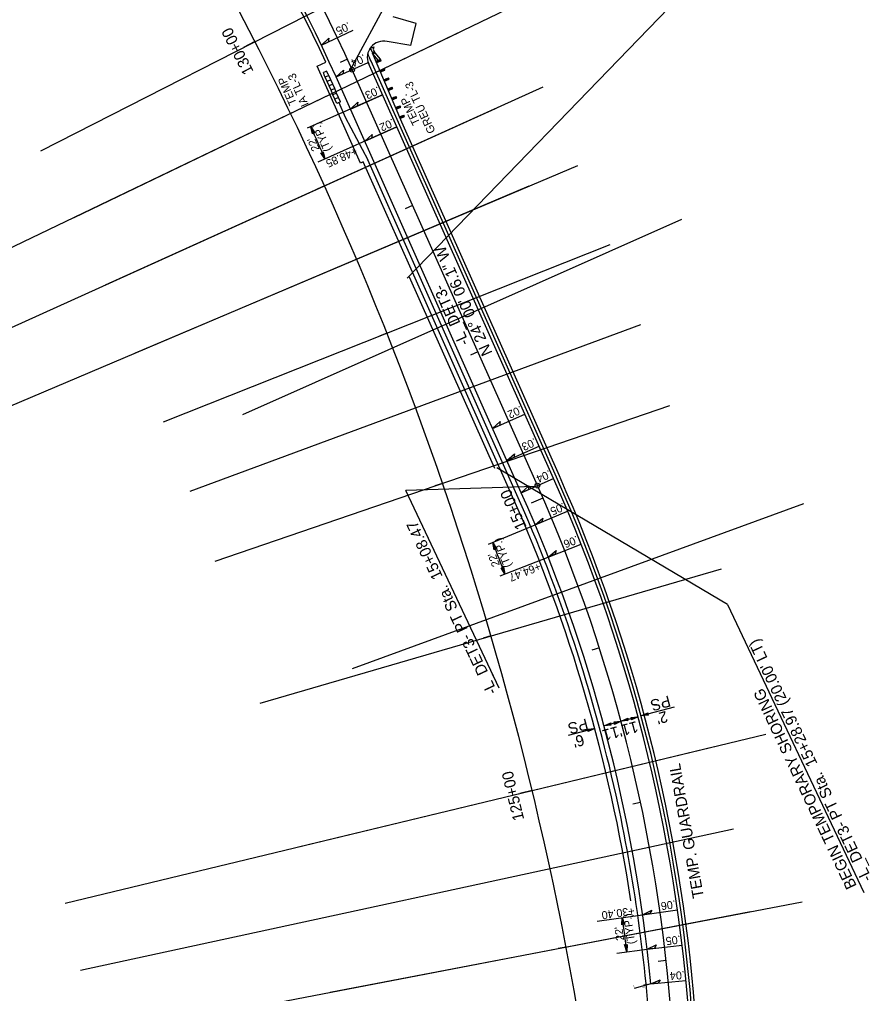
# Model space of a CAD drawing. Extents: x 473658 to 481584, y 489119 to 506230.
# Drawn here: x 477538 to 478069, y 498967 to 499575 of the extents above; entities that cross this region are included whole.
import ezdxf

# ---------------------------------------------------------------- set-up
doc = ezdxf.new("R2010")
doc.units = 0
for name, color, linetype in [('Exist Structure Minor Culvert Topo', 7, 'Continuous'), ('Exist Structure Minor Pipes CMP 60 Inch', 7, 'Continuous'), ('Exist Structure Minor Pipes RCP 12 Inch Leader', 7, 'Continuous'), ('Prop Conc Barrier', 7, 'Continuous'), ('Prop Dimension', 7, 'Continuous'), ('Prop EOT', 7, 'Continuous'), ('Prop Guardrail', 7, 'Continuous'), ('Prop Guardrail Anchor Unit CELL', 7, 'Continuous'), ('Prop Horizontal Alignment', 7, 'Continuous'), ('Prop Horizontal Alignment Direction Label', 7, 'Continuous'), ('Prop Horizontal Alignment Station Label', 7, 'Continuous'), ('Prop Horizontal Alignment Tick Label', 7, 'Continuous'), ('Prop Horizontal Alignment Tick Large', 7, 'Continuous'), ('Prop Horizontal Alignment Tick Small', 7, 'Continuous'), ('Prop Paved Shoulder', 7, 'Continuous'), ('Prop Superelevation  Arrow CELL', 7, 'Continuous'), ('Prop Superelevation Label', 7, 'Continuous'), ('Scratch_Level_5', 7, 'Continuous'), ('Scratch_Level_6', 7, 'Continuous'), ('Sheet Plan And Profile CELL', 7, 'Continuous'), ('Sheet Profile Grid Major CELL', 7, 'Continuous')]:
    doc.layers.add(name, color=color, linetype=linetype)

msp = doc.modelspace()

# ---------------------------------------------------------------- linework, layer by layer
at = {"layer": 'Exist Structure Minor Pipes CMP 60 Inch'}
msp.add_line((477834.89, 499294.51), (477781.59, 499414.21), dxfattribs=at)
at = {"layer": 'Exist Structure Minor Pipes RCP 12 Inch Leader'}
for p, q in [((477728.91, 499542.35), (477728, 499541.94)), ((477728.59, 499540.01), (477728, 499541.94)), ((477728.99, 499539.1), (477728.59, 499540.01)), ((477729.83, 499542.76), (477728.91, 499542.35)), ((477731.28, 499540.12), (477728.99, 499539.1)), ((477730.87, 499541.03), (477729.83, 499542.76)), ((477731.28, 499540.12), (477730.87, 499541.03)), ((477732.5, 499537.38), (477731.28, 499540.12)), ((477730.21, 499536.36), (477728.99, 499539.1)), ((477732.5, 499537.38), (477730.21, 499536.36)), ((477731.43, 499533.62), (477730.21, 499536.36)), ((477733.72, 499534.64), (477731.43, 499533.62)), ((477733.72, 499534.64), (477732.5, 499537.38)), ((477734.94, 499531.9), (477733.72, 499534.64)), ((477732.65, 499530.88), (477731.43, 499533.62)), ((477734.94, 499531.9), (477732.65, 499530.88)), ((477733.87, 499528.14), (477732.65, 499530.88)), ((477736.16, 499529.16), (477733.87, 499528.14)), ((477735.09, 499525.4), (477733.87, 499528.14)), ((477736.16, 499529.16), (477734.94, 499531.9)), ((477737.38, 499526.41), (477736.16, 499529.16)), ((477737.38, 499526.41), (477735.09, 499525.4)), ((477736.31, 499522.66), (477735.09, 499525.4)), ((477738.6, 499523.67), (477736.31, 499522.66)), ((477738.6, 499523.67), (477737.38, 499526.41))]:
    msp.add_line(p, q, dxfattribs=at)
at = {"layer": 'Prop Conc Barrier'}
for p, q in [((477737.46, 499523.17), (477741.52, 499514.03)), ((477741.52, 499514.03), (477755.55, 499487.44)), ((477848.71, 499278.22), (477755.55, 499487.44))]:
    msp.add_line(p, q, dxfattribs=at)
for centre, radius, start, end in [((476947.96, 498877.15), 986, 12.49586, 24.00169), ((476946.95, 498877.04), 987.01, 3.25612, 12.49584)]:
    msp.add_arc(centre, radius, start, end, dxfattribs=at)
at = {"layer": 'Prop Dimension'}
for p, q in [((477946.79, 499145.57), (477926.26, 499140.05)), ((477924.33, 499139.53), (477903.08, 499133.82)), ((477897.29, 499132.26), (477880.64, 499127.79))]:
    msp.add_line(p, q, dxfattribs=at)
for points in [[(477918.25, 499137.09), (477913.7, 499136.67), (477917.87, 499138.62), (477917.52, 499137.7)], [(477919.78, 499139.11), (477924.33, 499139.53), (477920.16, 499137.58), (477920.51, 499138.5)], [(477930.8, 499140.47), (477926.26, 499140.05), (477930.42, 499141.99), (477930.07, 499141.07)], [(477892.74, 499131.84), (477897.29, 499132.26), (477893.12, 499130.31), (477893.47, 499131.24)], [(477907.63, 499134.24), (477903.08, 499133.82), (477907.24, 499135.77), (477906.89, 499134.84)], [(477909.16, 499136.25), (477913.7, 499136.67), (477909.54, 499134.73), (477909.89, 499135.65)]]:
    msp.add_lwpolyline(points, close=True, dxfattribs=at)
at = {"layer": 'Prop EOT'}
for p, q in [((477785.86, 499572.68), (477771.43, 499576.81)), ((477782.52, 499558.84), (477785.86, 499572.68)), ((477782.52, 499558.84), (477767.67, 499561.26)), ((477871.55, 499288.39), (477755.87, 499548.18)), ((477851.45, 499279.44), (477735.77, 499539.23))]:
    msp.add_line(p, q, dxfattribs=at)
for centre, radius, start, end in [((476923.64, 499177.62), 889, 24.00169, 44.89268), ((477765.32, 499551.54), 10, 76.42001, 203.9531), ((476947.96, 498877.15), 1011, 3.2561, 24.00169), ((476947.96, 498877.15), 989, 5.54082, 24.00169)]:
    msp.add_arc(centre, radius, start, end, dxfattribs=at)
at = {"layer": 'Prop Guardrail'}
msp.add_line((477875.2, 499290.02), (477776.8, 499511.01), dxfattribs=at)
msp.add_arc((476947.96, 498877.15), 1015, 4.49325, 24.00169, dxfattribs=at)
at = {"layer": 'Prop Guardrail Anchor Unit CELL'}
for p, q in [((477756.61, 499556.75), (477759.3, 499557.94)), ((477757.87, 499556.02), (477756.61, 499556.75)), ((477758.7, 499554.15), (477757.87, 499556.02)), ((477758.45, 499554.55), (477759.83, 499555.13)), ((477758.45, 499554.55), (477760.22, 499554.21)), ((477776.8, 499511.01), (477758.64, 499554.09)), ((477759.26, 499554.4), (477758.7, 499554.15)), ((477759.83, 499555.13), (477758.84, 499553.63)), ((477758.84, 499553.63), (477760.22, 499554.21)), ((477762.15, 499549.71), (477758.84, 499553.63)), ((477759.3, 499557.94), (477758.99, 499556.51)), ((477758.99, 499556.51), (477759.82, 499554.64)), ((477759.82, 499554.64), (477759.26, 499554.4)), ((477760.22, 499554.21), (477759.83, 499555.13)), ((477760.22, 499554.21), (477760.03, 499554.67)), ((477763.56, 499550.3), (477760.22, 499554.21)), ((477760.74, 499549.11), (477763.56, 499550.3)), ((477762.54, 499548.79), (477760.74, 499549.11)), ((477761.13, 499548.19), (477762.15, 499549.71)), ((477761.13, 499548.19), (477763.95, 499549.38)), ((477762.54, 499548.79), (477762.15, 499549.71)), ((477762.15, 499549.71), (477763.95, 499549.38)), ((477763.56, 499550.3), (477762.54, 499548.79)), ((477763.95, 499549.38), (477763.56, 499550.3)), ((477763.19, 499543.31), (477765.95, 499544.47)), ((477764.96, 499542.97), (477763.19, 499543.31)), ((477763.58, 499542.38), (477764.57, 499543.89)), ((477763.58, 499542.38), (477766.34, 499543.55)), ((477764.96, 499542.97), (477764.57, 499543.89)), ((477764.57, 499543.89), (477766.34, 499543.55)), ((477765.95, 499544.47), (477764.96, 499542.97)), ((477766.34, 499543.55), (477765.95, 499544.47)), ((477765.64, 499537.5), (477768.53, 499538.72)), ((477767.47, 499537.19), (477765.64, 499537.5)), ((477766.02, 499536.58), (477767.08, 499538.11)), ((477766.02, 499536.58), (477768.92, 499537.8)), ((477767.47, 499537.19), (477767.08, 499538.11)), ((477767.08, 499538.11), (477768.92, 499537.8)), ((477768.53, 499538.72), (477767.47, 499537.19)), ((477768.92, 499537.8), (477768.53, 499538.72)), ((477768.08, 499531.69), (477770.88, 499532.87)), ((477768.47, 499530.77), (477768.08, 499531.69)), ((477769.87, 499531.36), (477768.08, 499531.69)), ((477768.47, 499530.77), (477769.48, 499532.28)), ((477768.47, 499530.77), (477771.27, 499531.95)), ((477769.87, 499531.36), (477769.48, 499532.28)), ((477769.48, 499532.28), (477771.27, 499531.95)), ((477770.88, 499532.87), (477769.87, 499531.36)), ((477771.27, 499531.95), (477770.88, 499532.87)), ((477770.53, 499525.89), (477773.34, 499527.07)), ((477772.32, 499525.56), (477770.53, 499525.89)), ((477770.92, 499524.97), (477771.94, 499526.48)), ((477770.92, 499524.97), (477773.73, 499526.15)), ((477772.32, 499525.56), (477771.94, 499526.48)), ((477771.94, 499526.48), (477773.73, 499526.15)), ((477773.34, 499527.07), (477772.32, 499525.56)), ((477773.73, 499526.15), (477773.34, 499527.07)), ((477772.98, 499520.08), (477775.79, 499521.27)), ((477774.77, 499519.75), (477772.98, 499520.08)), ((477773.37, 499519.16), (477774.39, 499520.67)), ((477773.37, 499519.16), (477776.18, 499520.34)), ((477774.77, 499519.75), (477774.39, 499520.67)), ((477774.39, 499520.67), (477776.18, 499520.34)), ((477775.79, 499521.27), (477774.77, 499519.75)), ((477776.18, 499520.34), (477775.79, 499521.27)), ((477775.43, 499514.27), (477778.19, 499515.44)), ((477775.43, 499514.27), (477776.81, 499514.86)), ((477775.81, 499513.35), (477775.43, 499514.27)), ((477777.2, 499513.93), (477775.43, 499514.27)), ((477776.81, 499514.86), (477775.81, 499513.35)), ((477775.81, 499513.35), (477778.58, 499514.52)), ((477777.2, 499513.93), (477776.81, 499514.86)), ((477776.81, 499514.86), (477778.58, 499514.52)), ((477778.19, 499515.44), (477777.2, 499513.93)), ((477778.58, 499514.52), (477778.19, 499515.44))]:
    msp.add_line(p, q, dxfattribs=at)
at = {"layer": 'Prop Horizontal Alignment'}
msp.add_line((477861.5, 499283.92), (477745.82, 499543.71), dxfattribs=at)
for centre, radius, start, end in [((476923.64, 499177.62), 900, 24.00169, 46.49452), ((475792.47, 498595.18), 2125, 7.92268, 31.27221), ((476947.96, 498877.15), 1000, 3.2561, 24.00169)]:
    msp.add_arc(centre, radius, start, end, dxfattribs=at)
at = {"layer": 'Prop Horizontal Alignment Station Label'}
for p, q in [((477744.45, 499543.1), (477795.95, 499638.28)), ((477964.72, 499604.42), (477780.22, 499413.6)), ((477980.24, 499209.62), (477836.25, 499295.12)), ((477860.13, 499283.31), (477779.32, 499280.79)), ((477837.61, 499157.43), (477779.32, 499280.79)), ((477980.24, 499209.62), (478065.22, 499029.81))]:
    msp.add_line(p, q, dxfattribs=at)
for centre in [(477745.82, 499543.71), (477861.5, 499283.92)]:
    msp.add_circle(centre, 1.5, dxfattribs=at)
at = {"layer": 'Prop Horizontal Alignment Tick Large'}
for p, q in [((477685.16, 499561.27), (477678.04, 499557.63)), ((477864.91, 499276.16), (477857.58, 499272.97)), ((477858.24, 499093.41), (477850.46, 499091.53))]:
    msp.add_line(p, q, dxfattribs=at)
at = {"layer": 'Prop Horizontal Alignment Tick Small'}
for p, q in [((477742.89, 499550.23), (477738.34, 499548.16)), ((477728.52, 499471.17), (477723.96, 499469.1)), ((477783.59, 499458.89), (477779.02, 499456.85)), ((477767.58, 499379.12), (477762.93, 499377.28)), ((477824.27, 499367.53), (477819.7, 499365.5)), ((477802.27, 499285.34), (477797.54, 499283.72)), ((477832.51, 499190.03), (477827.71, 499188.63)), ((477900.18, 499182.59), (477895.42, 499181.06)), ((477925.92, 499085.96), (477921.03, 499084.91)), ((477879.39, 498995.68), (477874.48, 498994.74)), ((477941.89, 498987.24), (477936.92, 498986.69))]:
    msp.add_line(p, q, dxfattribs=at)
at = {"layer": 'Prop Paved Shoulder'}
for p, q in [((477724, 499546.01), (477729.42, 499548.43)), ((477873.37, 499289.21), (477757.7, 499549)), ((477750.99, 499485.4), (477724, 499546.01)), ((477752.81, 499486.22), (477750.99, 499485.4)), ((477781.02, 499422.86), (477752.81, 499486.22)), ((477845.97, 499277), (477781.02, 499422.86))]:
    msp.add_line(p, q, dxfattribs=at)
for centre, radius, start, end in [((476923.64, 499177.62), 887, 24.71106, 44.25141), ((476923.64, 499177.62), 913, 24.00169, 24.32799), ((476947.96, 498877.15), 1013, 3.2561, 24.00169), ((476947.96, 498877.15), 983, 8.62468, 24.00169)]:
    msp.add_arc(centre, radius, start, end, dxfattribs=at)
at = {"layer": 'Prop Superelevation  Arrow CELL'}
for points in [[(477726.69, 499558.99), (477731.25, 499563.37), (477730.87, 499560.97)], [(477735.77, 499539.23), (477740.44, 499543.5), (477740, 499541.12)], [(477744.72, 499519.14), (477749.39, 499523.4), (477748.95, 499521.02)], [(477721.14, 499503.61), (477720.03, 499508.04), (477722.59, 499504.23), (477721.63, 499504.43)], [(477753.67, 499499.04), (477758.34, 499503.31), (477757.9, 499500.92)], [(477727.78, 499492.43), (477728.89, 499488), (477726.33, 499491.82), (477727.29, 499491.62)], [(477833.55, 499319.64), (477838.22, 499323.91), (477837.78, 499321.52)], [(477842.5, 499299.54), (477847.17, 499303.81), (477846.73, 499301.42)], [(477851.45, 499279.44), (477856.12, 499283.71), (477855.67, 499281.33)], [(477860.08, 499259.46), (477864.84, 499263.63), (477864.35, 499261.25)], [(477834.51, 499243.86), (477833.6, 499248.33), (477835.99, 499244.41), (477835.03, 499244.65)], [(477868.28, 499239.3), (477873.13, 499243.36), (477872.58, 499240.99)], [(477840.3, 499233.18), (477841.21, 499228.7), (477838.82, 499232.63), (477839.77, 499232.38)], [(477927.19, 499015.87), (477932.85, 499018.69), (477931.77, 499016.52)], [(477914.2, 499009.49), (477914.37, 499014.05), (477915.77, 499009.68), (477914.9, 499010.14)], [(477917.45, 498997.34), (477917.29, 498992.77), (477915.89, 498997.15), (477916.76, 498996.69)], [(477930, 498994.29), (477935.72, 498996.98), (477934.6, 498994.83)], [(477932.34, 498972.65), (477938.12, 498975.22), (477936.95, 498973.09)]]:
    msp.add_lwpolyline(points, close=True, dxfattribs=at)
at = {"layer": 'Prop Superelevation Label'}
for p, q in [((477726.69, 499558.99), (477746.56, 499568.42)), ((477735.77, 499539.23), (477755.87, 499548.18)), ((477764.82, 499528.09), (477717.77, 499507.14)), ((477744.72, 499519.14), (477764.82, 499528.09)), ((477773.77, 499507.99), (477724.49, 499486.05)), ((477753.67, 499499.04), (477773.77, 499507.99)), ((477833.55, 499319.64), (477853.65, 499328.59)), ((477842.5, 499299.54), (477862.6, 499308.49)), ((477851.45, 499279.44), (477871.55, 499288.39)), ((477860.08, 499259.46), (477880.37, 499267.97)), ((477831.07, 499247.3), (477860.08, 499259.46)), ((477868.28, 499239.3), (477888.75, 499247.35)), ((477838.19, 499227.46), (477868.28, 499239.3)), ((477927.19, 499015.87), (477948.97, 499018.96)), ((477898.72, 499011.84), (477927.19, 499015.87)), ((477911.02, 498991.93), (477930, 498994.29)), ((477930, 498994.29), (477951.85, 498996.89)), ((477932.34, 498972.65), (477954.24, 498974.77))]:
    msp.add_line(p, q, dxfattribs=at)
for centre, start, end in [((480037.54, 500520.04), 203.58982, 204.08621), ((480193.62, 500156.67), 201.05046, 201.52805), ((480421.1, 499347.61), 187.57958, 188.06624)]:
    msp.add_arc(centre, 2528.83, start, end, dxfattribs=at)
at = {"layer": 'Scratch_Level_5'}
for p, q in [((477437.03, 499386.41), (477812.95, 499567.27)), ((477455.19, 499347.5), (477835.26, 499519.46)), ((477472.43, 499308.17), (477856.44, 499471.15)), ((477566.6, 499023.07), (477972.13, 499120.88)), ((477576.18, 498981.21), (477983.9, 499069.45)), ((477584.76, 498939.14), (477994.45, 499017.76))]:
    msp.add_line(p, q, dxfattribs=at)
at = {"layer": 'Scratch_Level_6'}
for p, q in [((477677.52, 499328.34), (477951.58, 499450.37)), ((477746.07, 499169.62), (478027.75, 499272.84)), ((477932.34, 498972.65), (477921.85, 498969.76)), ((477927.98, 498971.76), (477930.29, 498972.4))]:
    msp.add_line(p, q, dxfattribs=at)
msp.add_lwpolyline([(477927.98, 498971.76), (477928.51, 498972.11), (477928.43, 498971.88)], close=True, dxfattribs=at)
at = {"layer": 'Sheet Plan And Profile CELL'}
for p, q in [((477551.56, 499493.08), (477818.77, 499629.47)), ((477572.2, 499451.44), (477842.54, 499581.51)), ((477591.85, 499409.33), (477865.18, 499533)), ((477610.51, 499366.77), (477886.67, 499483.98)), ((477628.16, 499323.78), (477907, 499434.46)), ((477644.79, 499280.39), (477926.16, 499384.48)), ((477660.4, 499236.62), (477944.14, 499334.06)), ((477688.51, 499148.04), (477976.52, 499232.02)), ((477712.42, 499058.24), (478004.06, 499128.58)), ((477732.08, 498967.41), (478026.7, 499023.95))]:
    msp.add_line(p, q, dxfattribs=at)

# ---------------------------------------------------------------- texts
at = {"layer": 'Exist Structure Minor Culvert Topo'}
for s, p in [('IA TL-3', (477718.89, 499521.99)), ('TEMP', (477711.36, 499522.82))]:
    msp.add_text(s, height=5, rotation=113.83419, dxfattribs=at).set_placement(p)
at = {"layer": 'Prop Dimension'}
for s, p in [('PS', (477943.51, 499152.91)), ("2'", (477941.77, 499143.25)), ('PS', (477892.05, 499138.5)), ("11'", (477911.52, 499133.74)), ("11'", (477923.28, 499136.9)), ("6'", (477889.66, 499128.67))]:
    msp.add_text(s, height=7, rotation=195.04147, dxfattribs=at).set_placement(p)
at = {"layer": 'Prop Guardrail Anchor Unit CELL'}
for s, p in [('GREU TL-3', (477798, 499505.3)), ('TEMP. ', (477788.31, 499510.47))]:
    msp.add_text(s, height=5, rotation=115.2938, dxfattribs=at).set_placement(p)
at = {"layer": 'Prop Horizontal Alignment Direction Label'}
for s, p in [('N 24%%d 00\' 06.1" W', (477833.59, 499366.85)), ('-L_DET3-', (477819.07, 499373.13))]:
    msp.add_text(s, height=7, rotation=114.00169, dxfattribs=at).set_placement(p)
at = {"layer": 'Prop Horizontal Alignment Station Label'}
for s, p in [('-L_DET3- PT Sta.  15+08.47', (477836.59, 499155.2)), ("-L_DET3- PT Sta.  15+28.97 (20.00' LT)", (478070.49, 499038.32)), ('BEGIN TEMPORARY SHORING', (478061, 499033.84))]:
    msp.add_text(s, height=7, rotation=115.2938, dxfattribs=at).set_placement(p)
at = {"layer": 'Prop Horizontal Alignment Tick Label'}
for s, rotation, p in [('130+00', 117.04126, (477684.51, 499542.75)), ('15+00', 113.51617, (477854.87, 499258.17)), ('125+00', 103.5599, (477853.3, 499075.49))]:
    msp.add_text(s, height=7, rotation=rotation, dxfattribs=at).set_placement(p)
at = {"layer": 'Prop Superelevation  Arrow CELL'}
for s, rotation, p in [('.05', 205.40295, (477743.46, 499573.68)), ('.04', 204.00169, (477753.06, 499553.58)), ('.03', 204.00169, (477761.81, 499533.4)), ('.02', 204.00169, (477770.91, 499513.36)), ('+48.85', 204.00169, (477747.75, 499495.38)), ('.02', 204.00169, (477850.79, 499333.96)), ('.03', 204.00169, (477859.59, 499313.8)), ('.04', 204.00169, (477868.73, 499293.79)), ('.05', 202.74064, (477877.52, 499273.36)), ('.06', 201.47961, (477885.92, 499252.77)), ('+64.47', 201.47961, (477862.43, 499235.99)), ('.06', 188.06279, (477947.47, 499024.88)), ('+30.40', 188.06279, (477921.75, 499020.74)), ('.05', 186.80176, (477950.59, 499002.86)), ('.04', 185.54082, (477953.28, 498980.78))]:
    msp.add_text(s, height=5, rotation=rotation, dxfattribs=at).set_placement(p)
at = {"layer": 'Prop Superelevation Label'}
for s, rotation, p in [('(TYP.)', 113.79181, (477732.97, 499493.81)), ("22'", 113.79181, (477725.7, 499494.07)), ('(TYP.)', 111.30765, (477845.43, 499233.8)), ("22'", 111.30765, (477838.18, 499234.37)), ('(TYP.)', 97.79122, (477922.57, 498997.75)), ("22'", 97.79122, (477915.65, 499000))]:
    msp.add_text(s, height=5, rotation=rotation, dxfattribs=at).set_placement(p)
at = {"layer": 'Scratch_Level_6'}
for s, rotation, p in [('1677.85', 110.07041, (477932.81, 498972.82)), ('1677.44', 110.07041, (477922.32, 498969.94)), ("10.88'", 195.36827, (477928.71, 498971.13)), ('.038', 195.36827, (477929.8, 498972.99))]:
    msp.add_text(s, height=0.5, rotation=rotation, dxfattribs=at).set_placement(p)
at = {"layer": 'Sheet Profile Grid Major CELL'}
for s, p in [('GUARDRAIL', (477960.09, 499057.1)), ('TEMP. ', (477965.49, 499026.83))]:
    msp.add_text(s, height=7, rotation=100.12493, dxfattribs=at).set_placement(p)

doc.saveas('drawing.dxf')
